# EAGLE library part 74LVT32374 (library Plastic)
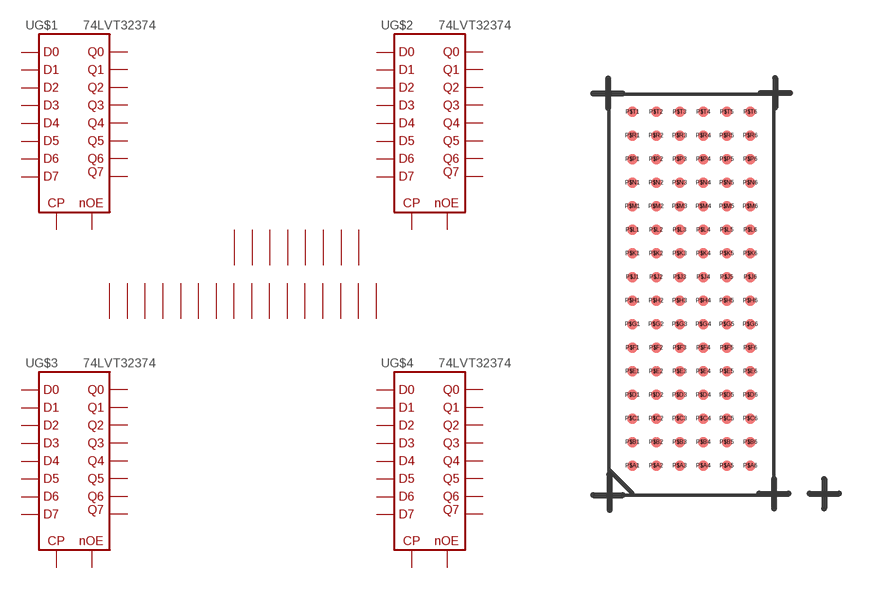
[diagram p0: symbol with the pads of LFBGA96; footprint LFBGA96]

Designator prefix -; gates G$1=74LVT32374 G$2=74LVT32374 G$3=74LVT32374 G$4=74LVT32374 G$5=PWR_74LVT32374

## 74LVT32374  [LFBGA96]
P$A1  G$1:P$Q1  out
P$A2  G$1:P$Q0  out
P$A3  G$1:P$NOE  in
P$A4  G$1:P$CP  in
P$A5  G$1:P$D0  in
P$A6  G$1:P$D1  in
P$B1  G$1:P$Q3  out
P$B2  G$1:P$Q2  out
P$B3  G$5:P$B3  sup
P$B4  G$5:P$B4  sup
P$B5  G$1:P$D2  in
P$B6  G$1:P$D3  in
P$C1  G$1:P$Q5  out
P$C2  G$1:P$Q4  out
P$C3  G$5:P$C3  sup
P$C4  G$5:P$C4  sup
P$C5  G$1:P$D4  in
P$C6  G$1:P$D5  in
P$D1  G$1:P$Q7  out
P$D2  G$1:P$Q6  out
P$D3  G$5:P$D3  sup
P$D4  G$5:P$D4  sup
P$D5  G$1:P$D6  in
P$D6  G$1:P$D7  in
P$E1  G$2:P$Q1  out
P$E2  G$2:P$Q0  out
P$E3  G$5:P$E3  sup
P$E4  G$5:P$E4  sup
P$E5  G$2:P$D0  in
P$E6  G$2:P$D1  in
P$F1  G$2:P$Q3  out
P$F2  G$2:P$Q2  out
P$F3  G$5:P$F3  sup
P$F4  G$5:P$F4  sup
P$F5  G$2:P$D2  in
P$F6  G$2:P$D3  in
P$G1  G$2:P$Q5  out
P$G2  G$2:P$Q4  out
P$G3  G$5:P$G3  sup
P$G4  G$5:P$G4  sup
P$G5  G$2:P$D4  in
P$G6  G$2:P$D5  in
P$H1  G$2:P$Q6  out
P$H2  G$2:P$Q7  out
P$H3  G$2:P$NOE  in
P$H4  G$2:P$CP  in
P$H5  G$2:P$D7  in
P$H6  G$2:P$D6  in
P$J1  G$3:P$Q1  out
P$J2  G$3:P$Q0  out
P$J3  G$3:P$NOE  in
P$J4  G$3:P$CP  in
P$J5  G$3:P$D0  in
P$J6  G$3:P$D1  in
P$K1  G$3:P$Q3  out
P$K2  G$3:P$Q2  out
P$K3  G$5:P$K3  sup
P$K4  G$5:P$K4  sup
P$K5  G$3:P$D2  in
P$K6  G$3:P$D3  in
P$L1  G$3:P$Q5  out
P$L2  G$3:P$Q4  out
P$L3  G$5:P$L3  sup
P$L4  G$5:P$L4  sup
P$L5  G$3:P$D4  in
P$L6  G$3:P$D5  in
P$M1  G$3:P$Q7  out
P$M2  G$3:P$Q6  out
P$M3  G$5:P$M3  sup
P$M4  G$5:P$M4  sup
P$M5  G$3:P$D6  in
P$M6  G$3:P$D7  in
P$N1  G$4:P$Q1  out
P$N2  G$4:P$Q0  out
P$N3  G$5:P$N3  sup
P$N4  G$5:P$N4  sup
P$N5  G$4:P$D0  in
P$N6  G$4:P$D1  in
P$P1  G$4:P$Q3  out
P$P2  G$4:P$Q2  out
P$P3  G$5:P$P3  sup
P$P4  G$5:P$P4  sup
P$P5  G$4:P$D2  in
P$P6  G$4:P$D3  in
P$R1  G$4:P$Q5  out
P$R2  G$4:P$Q4  out
P$R3  G$5:P$R3  sup
P$R4  G$5:P$R4  sup
P$R5  G$4:P$D4  in
P$R6  G$4:P$D5  in
P$T1  G$4:P$Q6  out
P$T2  G$4:P$Q7  out
P$T3  G$4:P$NOE  in
P$T4  G$4:P$CP  in
P$T5  G$4:P$D7  in
P$T6  G$4:P$D6  in

## Footprint LFBGA96 (pad centres in mm)
smd 0.35 x 0.35: P$A1 -2,-6.054; P$A2 -1.2,-6.054; P$A3 -0.4,-6.054; P$A4 0.4,-6.054; P$A5 1.2,-6.054; P$A6 2,-6.054; P$B1 -2,-5.254; P$B2 -1.2,-5.254; P$B3 -0.4,-5.254; P$B4 0.4,-5.254; P$B5 1.2,-5.254; P$B6 2,-5.254; P$C1 -2,-4.454; P$C2 -1.2,-4.454; P$C3 -0.4,-4.454; P$C4 0.4,-4.454; P$C5 1.2,-4.454; P$C6 2,-4.454; P$D1 -2,-3.654; P$D2 -1.2,-3.654; P$D3 -0.4,-3.654; P$D4 0.4,-3.654; P$D5 1.2,-3.654; P$D6 2,-3.654; P$E1 -2,-2.854; P$E2 -1.2,-2.854; P$E3 -0.4,-2.854; P$E4 0.4,-2.854; P$E5 1.2,-2.854; P$E6 2,-2.854; P$F1 -2,-2.054; P$F2 -1.2,-2.054; P$F3 -0.4,-2.054; P$F4 0.4,-2.054; P$F5 1.2,-2.054; P$F6 2,-2.054; P$G1 -2,-1.254; P$G2 -1.2,-1.254; P$G3 -0.4,-1.254; P$G4 0.4,-1.254; P$G5 1.2,-1.254; P$G6 2,-1.254; P$H1 -2,-0.454; P$H2 -1.2,-0.454; P$H3 -0.4,-0.454; P$H4 0.4,-0.454; P$H5 1.2,-0.454; P$H6 2,-0.454; P$J1 -2,0.346; P$J2 -1.2,0.346; P$J3 -0.4,0.346; P$J4 0.4,0.346; P$J5 1.2,0.346; P$J6 2,0.346; P$K1 -2,1.146; P$K2 -1.2,1.146; P$K3 -0.4,1.146; P$K4 0.4,1.146; P$K5 1.2,1.146; P$K6 2,1.146; P$L1 -2,1.946; P$L2 -1.2,1.946; P$L3 -0.4,1.946; P$L4 0.4,1.946; P$L5 1.2,1.946; P$L6 2,1.946; P$M1 -2,2.746; P$M2 -1.2,2.746; P$M3 -0.4,2.746; P$M4 0.4,2.746; P$M5 1.2,2.746; P$M6 2,2.746; P$N1 -2,3.546; P$N2 -1.2,3.546; P$N3 -0.4,3.546; P$N4 0.4,3.546; P$N5 1.2,3.546; P$N6 2,3.546; P$P1 -2,4.346; P$P2 -1.2,4.346; P$P3 -0.4,4.346; P$P4 0.4,4.346; P$P5 1.2,4.346; P$P6 2,4.346; P$R1 -2,5.146; P$R2 -1.2,5.146; P$R3 -0.4,5.146; P$R4 0.4,5.146; P$R5 1.2,5.146; P$R6 2,5.146; P$T1 -2,5.946; P$T2 -1.2,5.946; P$T3 -0.4,5.946; P$T4 0.4,5.946; P$T5 1.2,5.946; P$T6 2,5.946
